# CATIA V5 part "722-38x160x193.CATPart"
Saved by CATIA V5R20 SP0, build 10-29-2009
Part number: 722-38x160x193
Definition: NONE
Nomenclature: 722-38x160x193
Source: Unknown
Description: 722-38x160x193
Bounding box of the stored display mesh (mm): x -19 to 19, y -19 to 19, z -145 to 48
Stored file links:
  C:\Users\Utente\Desktop\IO LAVORO\3D X SITO CF\X SITO\722\722-38x160x193.CATPart

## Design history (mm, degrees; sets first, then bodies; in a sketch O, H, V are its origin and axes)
Body1 "722-38x160x193" (main body)
  Solid1: solid without history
